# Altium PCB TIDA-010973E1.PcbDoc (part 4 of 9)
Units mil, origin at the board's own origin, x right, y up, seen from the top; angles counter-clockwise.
Board outline 5166 x 3669 mil, 8 copper layers (L01 - TOP, L02 - GND, L03 - SIG, L04 - GND, L05 - PWR, L06 - SIG, L07 - GND, L08 - BOTTOM), stack 61.7 mil thick; 677 components, 493 nets, 2522 pads, 1424 vias.
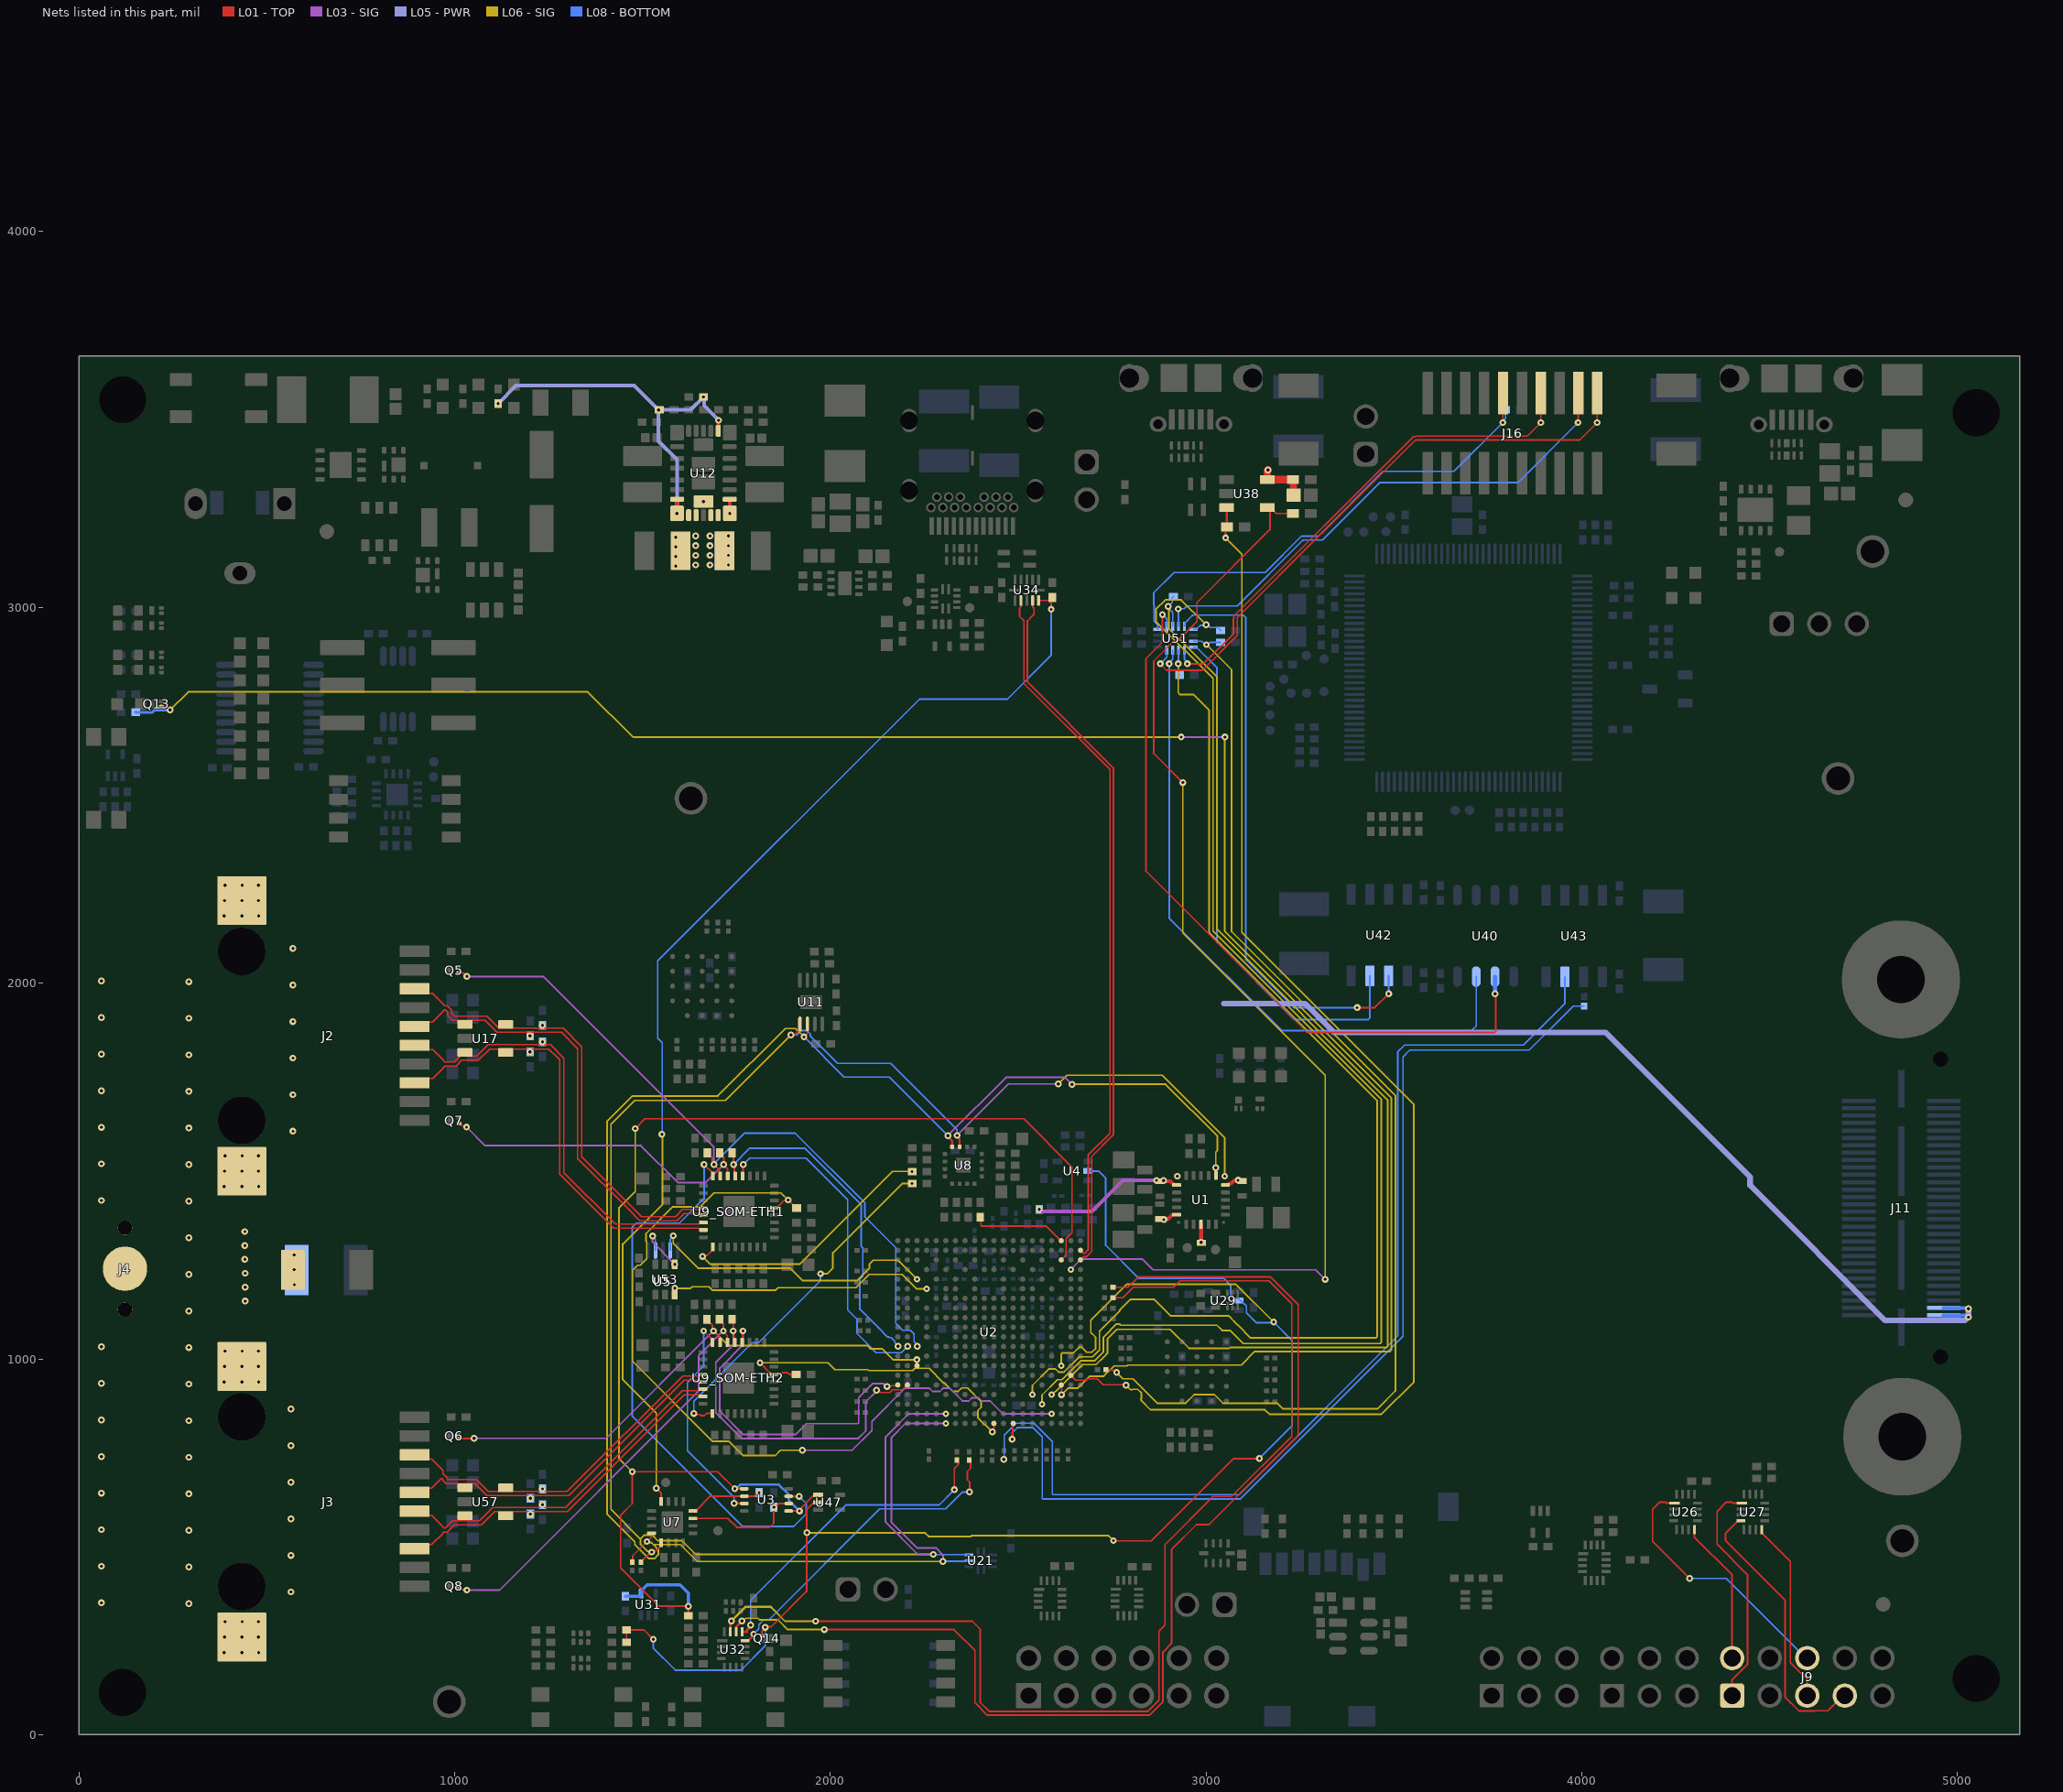
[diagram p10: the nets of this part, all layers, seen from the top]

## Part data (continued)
R167: library part CMP-0026413-2, "RES, 4.87 k, 1%, 0.063 W, AEC-Q200 Grade 0, 0402", Manufacturer=Vishay-Dale, Power_W=63mW, Supplier Part Number 1=541-4.87KLCT-ND, TempCo="100 ppm/C", Tolerance_%=1%, Value2=0.063W, Value_Code=4k87, ValueDisplayed=4.87k
R168: library part CMP-0078244-2, "RES, 30.0 k, 1%, 0.063 W, AEC-Q200 Grade 0, 0402", Manufacturer=Vishay-Dale, Power_W=63mW, Supplier Part Number 1=541-30.0KLCT-ND, TempCo="100 ppm/C", Tolerance_%=1%, Value2=0.063W, Value_Code=30k0, ValueDisplayed=30.0k
R216: library part CMP-0026022-3, "RES, 150, 1%, 0.063 W, AEC-Q200 Grade 0, 0402", Manufacturer=Vishay-Dale, Power_W=63mW, Supplier Part Number 1=541-150LCT-ND, TempCo="100 ppm/C", Tolerance_%=1%, Value2=0.063W, Value_Code=150R, ValueDisplayed=150
R218: library part CMP-0027615-1, "RES, 33.0, 1%, 0.05 W, 0201", Manufacturer="Yageo America", Power_W=50mW, Supplier Part Number 1=311-33.0MCT-ND, TempCo="200 ppm/C", Tolerance_%=1%, Value2=0.05W, Value_Code=33R0, ValueDisplayed=33.0
R222: library part CMP-0093210-1, "Jumper 0.063W, 1/16W Chip Resistor 0402 (1005 Metric) - Thick Film", Digikey Part Number=541-4062-1-ND, Manufacturer=Vishay, Mouser Part Number=71-CRCW04020000Z0EDC, Operating Temperature Range="-55°C to +155°C", Power_W=63mW
SH-J1 SH-J2: library part CMP-0003761-2, "Shunt, 2.54mm, Gold, Black", Manufacturer="Wurth Elektronik", Supplier Part Number 1=732-2678-ND
SW1 SW6: library part CMP-0093176-1, "Dip Switch SPST 4 Position Surface Mount Slide (Standard) Actuator 25mA 24VDC", Coil Resistance_ohm=100mΩ, Contact Current Rating=25mA, Digikey Part Number=732-3854-1-ND, Manufacturer=Wurth, Mouser Part Number=710-416131160804, Operating Temperature Range="-40°C to +85°C"
SW2 SW4 SW5: library part CMP-0093456-1, "Tactile Switch SPST-NO Side Actuated Surface Mount, Right Angle", Coil Resistance_ohm=100mΩ, Contact Current Rating=50mA, Digikey Part Number=732-7057-1-ND, Manufacturer="Wurth Electronics", Mouser Part Number=710-434351045816, Operating Force=160gf, Operating Temperature Range="-40°C to +85°C"
SW3: library part CMP-0124547-1, "Dip Switch Hexadecimal 16 Position Surface Mount Rotary for Tool Actuator 100mA 42VDC", Coil Resistance_ohm=80mΩ, Contact Current Rating=100mA, CurrentRating_mA=400mA, Digikey Part Number=732-6989-1-ND, Manufacturer=Wurth, Mouser Part Number=710-428542320816, Operating Force=150gf, Operating Temperature Range="-60°C to +125°C"
TP1 TP6 TP7 TP8 TP9 TP10 TP11 TP12 TP13 TP14 TP15 TP16 TP17 TP18 TP19 TP20 TP21 TP22 TP23 TP24 TP25 TP26 TP27 TP29 TP30 TP32 TP33: library part CMP-0078143-4, "TEST POINT.  No entry in BOM.", Manufacturer=N/A
TP2 TP3 TP4 TP5 TP31: library part CMP-0055148-2, "Test Point, Multipurpose, Black, TH", Color=Black, Manufacturer="Keystone Electronics", Supplier Part Number 1=36-5011-ND
U1: library part CMP-0121651-1, "Integrated Power Management IC for ARM Cortex®—Low Power Processors and FPGAs", Manufacturer="Texas Instruments", Max Supply Voltage=5.5V, Min Supply Voltage=2.5V, Operating Temperature Range="-40°C to +125°C", Output Voltage=0.6-3.4/0.6-3.4/0.6-3.3/0.6-3.3V
U2: library part CMP-0126016-1, "ARM® Cortex®-R5F Sitara™ Microcontroller IC 32-Bit Dual-Core 500MHz 512KB (512K x 8) Tightly Coupled Memory (TCM) 304-NFBGA (13.25x13.25)", Digikey Part Number=296-AM2612AOFFHIZFGRCT-ND, Frequency_Fixed=500MHz, Manufacturer="Texas Instruments", Max Supply Voltage=3.465V, Min Supply Voltage=1.14V, Mouser Part Number=595-AM2612AOFFHIZFGR, Operating Temperature Range="-40°C to +125°C"
U3: library part CMP-0051796-2, "Dual 2-Input Positive-AND Gate, DCU0008A (VSSOP-8)", F @ Nom Voltage(Max)(Mhz)=150, Generic Part Number=SN74LVC2G08, ICC @ Nom Voltage(Max)(mA)=0.01, Manufacturer="Texas Instruments", Operating Temperature Range="-40 to 125 C", Rating=Catalog, tpd @ Nom Voltage(Max)(ns)=9.8,5.8,5.3,4.8, Voltage(Nom)(V)=1.8,2.5,3.3,5
U4 U29: library part CMP-0051263-2, "Single 2-Input Positive–AND Gate with Open Drain Output, DCK0005A, LARGE T&R", F @ Nom Voltage(Max)(Mhz)=75, Generic Part Number=SN74AHC1G09, ICC @ Nom Voltage(Max)(mA)=0.01, Manufacturer="Texas Instruments", Operating Temperature Range(C)="-40 to 85", Rating=Catalog, tpd @ Nom Voltage(Max)(ns)=11,7.5, Voltage(Nom)(V)=3.3,5
U5: library part CMP-0067419-2, "2-Channel, 2:1 Analog Switch with Low On-State Resistance (1ohm) and Powered Off Protection, DGS0010A (VSSOP-10)", Alternate Manufacturer="Texas Instruments", Alternate PartNumber=TS5A23159DGST, Operating Temperature Range="-40 to 85 C", Rating=Catalog
U6: library part CMP-0051428-5, "Single Bus Buffer Gate With 3-State Outputs, DSF0006A, LARGE T&R", Alternate Manufacturer="Texas Instruments", F @ Nom Voltage(Max)(Mhz)=150, Generic Part Number=SN74LVC1G125, ICC @ Nom Voltage(Max)(mA)=0.01, Operating Temperature Range(C)="-40 to 125,-40 to 85", Rating=Catalog, tpd @ Nom Voltage(Max)(ns)=9,5.5,4.5,4, Voltage(Nom)(V)=1.8,2.5,3.3,5
U7 U23: library part CMP-0043157-2, "Low-Voltage 8-Bit I2C and SMBus I/O Expander, 1.65 to 5.5 V, -40 to 85 degC, 16-pin QFN (RGT), Green (RoHS & no Sb/Br)", 5V Tolerant I/O=Yes, Manufacturer="Texas Instruments", Max Frequency(kHz)=400
U8: library part CMP-0126121-1, "5 output reference-less clock generator with bulk acoustic wave (BAW) 16-TQFN -40 to 85", Digikey Part Number=296-LMK3C0105V33RERRTR-ND, Manufacturer="Texas Instruments", Max Frequency=200MHz, Max Supply Voltage=3.465V, Min Supply Voltage=1.71V, Mouser Part Number=595-LMK3C0105V33RERR, Operating Temperature Range="-40°C to +85°C"
U9_SOM-ETH1 U9_SOM-ETH2: library part CMP-0124715-2, "Deterministic, Low-Latency, Low-Power, 10/100 Mbps, Industrial Ethernet PHY", Manufacturer="Texas Instruments", Max Supply Voltage=3.6V, Min Supply Voltage=1.62V, Operating Temperature Range="-40°C to +85°C"
U10: library part CMP-0122153-1, "1.8V 64M-BIT [x 1/x 8] Read-While-Write octaflash Memory", Frequency_Fixed=200MHz, Manufacturer=Macronix, Max Supply Voltage=2V, Min Supply Voltage=1.7V, Nominal Supply Current=18-140mA, Operating Temperature Range="-40°C to +125°C"
U11: library part CMP-0126419-1, "EEPROM Serial-I2C 1M-bit 128K x 8 2.5V/3.3V/5V 8-Pin UDFN EP T/R", Digikey Part Number=CAT24M01HU5I-GT3OSCT-ND, Frequency_Fixed=1MHz, Manufacturer=onsemi, Max Supply Voltage=5.5V, Min Supply Voltage=1.8V, Mouser Part Number=863-CAT24M01HU5I-GT3, Nominal Supply Current=1-5mA, Operating Temperature Range="-40°C to +85°C"
U12: library part CMP-0092030-4, "3-V to 36-V Input, 1-V to 6-V Output, 3-A Power Module", Manufacturer="Texas Instruments", Max Supply Voltage=36V, Min Supply Voltage=3V, Operating Temperature Range=to, Output Voltage=1-6V, Switching Frequency=200-2200kHz
U13: library part CMP-0081714-3, "33 V Bidirectional Flat-Clamp Surge Protection Device, DRB0008A (VSON-8)", Alternate Manufacturer="Texas Instruments", Alternate PartNumber=TVS3301DRBR, Operating Temperature Range="-40 to 125 C", Rating=Catalog
U14 U15: library part CMP-0013281-4, "Low Iq Always ON Smart Diode Controller, DBV0006A (SOT-23-6)", Alternate Manufacturer="Texas Instruments", Alternate PartNumber=LM74700QDBVTQ1
U16: library part CMP-0122758-1, "DRAM IoT RAM 128Mb OPI (x8) DDR 200MHz, 1.8V, Ext. Temp., BGA24", Frequency_Fixed=200MHz, Manufacturer="AP Memory", Max Supply Voltage=1.98V, Min Supply Voltage=1.62V, Mouser Part Number=878-APS12808L-OBMXBA, Nominal Supply Current=4-22mA, Operating Temperature Range="-40°C to +105°C"
U17 U57: library part CMP-0085635-1, "Data-Line Surge and ESD Protection Diode Array, DBV0005A (SOT-23-5)", Alternate Manufacturer="Texas Instruments", Operating Temperature Range="-40 to 125 C", Rating=Catalog
U19: library part CMP-0043123-1, "Low-Capacitance + / - 15 kV ESD Protection Array for High-Speed Data Interfaces, 6 Channels, -40 to +85 degC, 10-pin UQFN (RSE), Green (RoHS & no Sb/Br)", Breakdown Voltage(Min)(V)=11, IO Capacitance(Typ)(pF)=1.5, IO Leakage Current(nA)=1, Manufacturer="Texas Instruments"
U20: library part CMP-0051412-4, "Single Buffer/Driver With Open-Drain Output, DRY0006A (USON-6)", F @ Nom Voltage(Max)(Mhz)=150, Generic Part Number=SN74LVC1G07, ICC @ Nom Voltage(Max)(mA)=0.01, Manufacturer="Texas Instruments", Operating Temperature Range="-40 to 125 C", Operating Temperature Range(C)="-40 to 125,-40 to 85", Rating=Catalog, tpd @ Nom Voltage(Max)(ns)=8.6,6,4.7,4, Voltage(Nom)(V)=1.8,2.5,3.3,5
U21: library part CMP-0122684-1, "2-pF, 3.3-V, 2:1 (SPDT), 2-channel, switch with 1.8-V compatible logic", Digikey Part Number=296-TMUX121NKGRCT-ND, Manufacturer="Texas Instruments", Max Supply Voltage=3.6V, Min Supply Voltage=3V, Mouser Part Number=595-TMUX121NKGR, Nominal Supply Current=1.3-11uA, On State Resistance=3.9Ω, Operating Temperature Range="-40°C to +125°C"
U22: library part CMP-0034642-1, "8-Bit Fast Mode Plus (FM+) I2C Bus Constant-Current LED Sink Driver, 3 to 5.5 V, -40 to 85 degC, 20-pin SOP (PW20), Green (RoHS & no Sb/Br)", Manufacturer="Texas Instruments"
U24: library part CMP-0043237-2, "Remote 4-Bit I2C and SMBus I/O Expander With Configuration Registers, DGK0008A (VSSOP-8)", 5V Tolerant I/O=Yes, Manufacturer="Texas Instruments", Max Frequency(kHz)=400
U25: library part CMP-0051707-3, "Single Schmitt-Trigger Buffer, DRL0005A, LARGE T&R", Alternate Manufacturer="Texas Instruments", F @ Nom Voltage(Max)(Mhz)=150, Generic Part Number=SN74LVC1G17, ICC @ Nom Voltage(Max)(mA)=0.01, Operating Temperature Range(C)="-40 to 125,-40 to 85", Rating=Catalog, tpd @ Nom Voltage(Max)(ns)=11,6.5,5.5,5, Voltage(Nom)(V)=1.8,2.5,3.3,5
U26 U27 U28 U49 U51 U52: library part CMP-0086167-3, "Low-capacitance, 2:1 (SPDT) 4-channel, powered-off protection switch with 1.8 V logic, RSV0016A (UQFN-16)", Alternate Manufacturer="Texas Instruments", Operating Temperature Range="-40 to 125 C", Rating=Catalog
U30: library part CMP-0051441-4, "Single Schmitt-Trigger Buffer, DRY0006A (USON-6)", F @ Nom Voltage(Max)(Mhz)=150, Generic Part Number=SN74LVC1G17, ICC @ Nom Voltage(Max)(mA)=0.01, Manufacturer="Texas Instruments", Operating Temperature Range="-40 to 125 C", Operating Temperature Range(C)="-40 to 125,-40 to 85", Rating=Catalog, tpd @ Nom Voltage(Max)(ns)=11,6.5,5.5,5, Voltage(Nom)(V)=1.8,2.5,3.3,5
U31: library part CMP-0051585-3, "Single 2-Input Positive-AND Gate, DRL0005A, LARGE T&R", Alternate Manufacturer="Texas Instruments", F @ Nom Voltage(Max)(Mhz)=150, Generic Part Number=SN74LVC1G08, ICC @ Nom Voltage(Max)(mA)=0.01, Operating Temperature Range(C)="-40 to 125,-40 to 85", Rating=Catalog, tpd @ Nom Voltage(Max)(ns)=4.5,6,4,5, Voltage(Nom)(V)=1.8,2.5,3.3,5
U32: library part CMP-0066450-2, "4-Bit Dual-Supply Bus Transceiver with Configurable Voltage-Level Shifting and 3-State Outputs, RSV0016A (UQFN-16)", Alternate Manufacturer="Texas Instruments"
U33: library part CMP-0073635-2, "USB Type-C Configuration Channel Logic and Port Control, RWB0012A (X2QFN-12)", Alternate Manufacturer="Texas Instruments", Operating Temperature Range="-40 to 85 C", Rating=Catalog
U34: library part CMP-0033722-2, "USB 2.0 High-Speed (480 Mbps) and Audio Switch, DP3T, 6.5 ohm RON, -40 to 85 degC, 12-Pin UQFN (RUT), Green (RoHS & no Sb/Br)", Manufacturer="Texas Instruments"
U35 U36 U44: library part CMP-0073612-3, "4-Channel ESD Protection Diode for USB Type-C and HDMI 2.0, DQA0010A (USON-10)", Alternate Manufacturer="Texas Instruments"
U37: library part CMP-0073678-3, "5.5V, 4A, 16mΩ Automotive Load Switch With Adjustable Rise Time and Optional Quick Output Discharge, DSG0008B (WSON-8)", Alternate Manufacturer="Texas Instruments", Alternate PartNumber=TPS22965TDSGTQ1
U38: library part CMP-0074276-1, "Single, Current-Limited, Power-Distribution Switch, DBV0005A (SOT-23-5)", Alternate Manufacturer="Texas Instruments", Alternate PartNumber=TPS2051BDBVT
U39: library part CMP-0051530-2, "Single 2-Input Positive-NOR Gate, DRL0005A, LARGE T&R", Alternate Manufacturer="Texas Instruments", F @ Nom Voltage(Max)(Mhz)=75, Generic Part Number=SN74AHC1G02, ICC @ Nom Voltage(Max)(mA)=0.01, Operating Temperature Range(C)="-40 to 125,-40 to 85", Rating=Catalog, tpd @ Nom Voltage(Max)(ns)=11.4,7.5, Voltage(Nom)(V)=3.3,5
U40: library part CMP-0029369-1, "25 Mbps Dual Channels, 2 / 0, Digital Isolator, 3.3 V / 5 V, -40 to +125 degC, 8-pin SOIC (D), Green (RoHS & no Sb/Br)", Insulation Rating(VRMS)=2500, Manufacturer="Texas Instruments", Rating=Catalog, Supply Voltage(s)(V)="3.3, 5"
U41: library part CMP-0029856-2, "Tiva C Series Microcontroller, 1024 KB Flash, 256 KB SRAM, 12 Bit, 20 Channels, -40 to 105 degC, 128-Pin TQFP (PDT), Green (RoHS & no Sb/Br), Tray", Manufacturer="Texas Instruments", Temperature Range="-40 to 105 degC"
U42 U43: library part CMP-0076059-2, "High Speed, Robust EMC Dual-Channel Digital Isolator, D0008B (SOIC-8)", Alternate Manufacturer="Texas Instruments", Alternate PartNumber=ISO7721D, Operating Temperature Range="-55 to 125 C", Rating=Catalog
U45: library part CMP-0036402-3, "Single Output High PSRR LDO, 1 A, Adjustable 1.2 to 5.5 V Output, 2.7 to 5.5 V Input, 8-pin SON (DRB), -40 to 125 degC, Green (RoHS & no Sb/Br)", Manufacturer="Texas Instruments"
U46: library part CMP-0033001-1, "Precision Micropower Shunt Voltage Reference, 0.5% accuracy, 2.5 V, 15 ppm / degC, 15 mA, -40 to 125 degC, 3-pin SOT-23 (DBZ), Green (RoHS & no Sb/Br)", Manufacturer="Texas Instruments", Rating=Catalog, Temp Coeff(Max)(ppm/ degree C)=100, Temp Coeff(Typ)(ppm/ degree C)=15
U47: library part CMP-0051558-2, "Single 2-Input Positive-AND Gate, DRL0005A, LARGE T&R", Alternate Manufacturer="Texas Instruments", F @ Nom Voltage(Max)(Mhz)=75, Generic Part Number=SN74AHC1G08, ICC @ Nom Voltage(Max)(mA)=0.01, Operating Temperature Range(C)="-55 to 125", Rating=Catalog, tpd @ Nom Voltage(Max)(ns)=12.3,7.9, Voltage(Nom)(V)=3.3,5
U48: library part CMP-0051903-4, "Dual Schmitt-Trigger Buffer, DRY0006A (USON-6)", F @ Nom Voltage(Max)(Mhz)=150, Generic Part Number=SN74LVC2G17, ICC @ Nom Voltage(Max)(mA)=0.01, Manufacturer="Texas Instruments", Operating Temperature Range="-40 to 125 C", Operating Temperature Range(C)="-40 to 125,-40 to 85", Rating=Catalog, tpd @ Nom Voltage(Max)(ns)=9.3,5.7,5.4,4.3, Voltage(Nom)(V)=1.8,2.5,3.3,5
U50: library part CMP-0122847-1, "5.5-V, 2-A, 52-mΩ load switch with adj. rise time and adj. output discharge", Digikey Part Number=296-46278-1-ND, Manufacturer="Texas Instruments", Max Supply Voltage=5.5V, Mouser Part Number=595-TPS22918DBVR, Nominal Supply Current=8.3-10.2uA, Operating Temperature Range="-40°C to +105°C"
U53: library part CMP-0074352-3, "1-Bit Bidirectional Voltage-Level Shifter for Open-Drain and Push-Pull Application, DCK0006A (SOT-SC70-6)", Alternate Manufacturer="Texas Instruments", Alternate PartNumber=TXS0101DCKT, Operating Temperature Range="-40 to 85,-55 to 125 C", Rating=Catalog
U54: library part CMP-0051682-2, "Single Inverter Gate, DRL0005A, LARGE T&R", Alternate Manufacturer="Texas Instruments", F @ Nom Voltage(Max)(Mhz)=75, Generic Part Number=SN74AHC1G04, ICC @ Nom Voltage(Max)(mA)=0.01, Operating Temperature Range(C)="-40 to 125", Rating=Catalog, tpd @ Nom Voltage(Max)(ns)=10.6,7.5, Voltage(Nom)(V)=3.3,5
U55: library part CMP-0081179-1, "Single-Bit Dual-Supply Bus Transceiver, DRL0006A (SOT-OTHER-6)", Alternate Manufacturer="Texas Instruments"
Y1: library part CMP-0004635-3, "Crystal, 16 MHz, 8pF, SMD", Frequency Stability=+/-30ppm, Frequency_Fixed=16MHz, Manufacturer=NDK, Supplier Part Number 1=644-1157-1-ND
ZZ1: library part CMP-0003616-3
ZZ2: library part CMP-0077236-1
ZZ3: library part CMP-0077237-1
ZZ4: library part CMP-0077238-1

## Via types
v1: diameter 18, hole 8, L01 - TOP to L08 - BOTTOM, tented both sides, 1389 vias
v2: diameter 19.68, hole 7.87, L01 - TOP to L08 - BOTTOM, 24 vias
v3: diameter 19.68, hole 7.87, L01 - TOP to L08 - BOTTOM, tented both sides, 11 vias

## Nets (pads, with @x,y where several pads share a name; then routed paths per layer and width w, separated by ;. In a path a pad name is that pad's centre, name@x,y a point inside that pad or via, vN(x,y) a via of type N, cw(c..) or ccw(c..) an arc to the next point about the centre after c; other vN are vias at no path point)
5V: C22.1 C23.1 C24.1 C25.1 C88.2 C89.2 C90.2 C99.1 C135.2 C136.1 J11.2 J11.4 R1.2 R60.2 R65.2 U1.4 U1.12 U1.19 U1.20 U1.24 U12.7 U12.8 U12.9 U12.10 U12.12 U12.13 U12.14 U12.15 U12.22 U12.30 U38.5 | length 4265
  L01 - TOP w10: v1(1592.09,3250.37) 1592.31,3250.59 1592.31,3287.56 U12.7@1592.53,3287.77 ; U12.22@1701.78,3469.86 1702.39,3470.47 1702.39,3497.39 v1(1703,3498) ; U12.15@1732.29,3287.77 1732.51,3287.56 1732.51,3250.59 v1(1732.72,3250.37) ; C24.1@2877.13,1472.95 2878.97,1474.78 v1(2886.93,1474.78) ; C24.1@2886.93,1473.33 2904.53,1473.33 U1.20@2914.99,1462.87 ; v1(2887.76,1370.82) 2889.29,1372.35 2898.65,1372.35 2910.35,1384.05 U1.24@2921.8,1384.05 ; U1.4@2986.76,1358.46 2986.84,1358.38 2986.84,1310.9 v1(2987.13,1310.61) ; U1.12@3051.72,1462.79 3058.46,1462.79 3062.22,1466.55 3066.94,1466.55 3074.47,1474.08 3083.61,1474.08 v1(3085.14,1475.61)
  L01 - TOP w20: v1(3165,3366) 3163.13,3364.13 U38.5@3163.13,3340.4 3163.33,3340.2 3225.63,3340.2 3225.83,3340 C136.1@3231.38,3340 3232.35,3339.02 3232.35,3299.98 C135.2@3233.33,3299 C135.2@3232.33,3298
  L03 - SIG w10: v1(2556.15,1398.17) 2558.31,1398.17 2563.48,1393 2696.72,1393 2779,1475.28 v1(2868.11,1475.28) 2868.36,1475.03 2886.68,1475.03 v1(2886.93,1474.78)
  L05 - PWR w10: v1(1116,3542.31) 1164.02,3590.33 1478.08,3590.33 v1(1542.76,3525.65) ; v1(1592.09,3250.37) 1592.09,3393.19 1542.76,3442.53 v1(1542.76,3525.65) ; v1(1703,3498) 1664.22,3536.78 1664.22,3558.47 v1(1662.68,3560) 1628.34,3525.65 v1(1542.76,3525.65)
  L05 - PWR w15: 3048,1946 3263,1946 3340,1869 4062.82,1869 4447.75,1484.07 4447.75,1462.43 4807.68,1102.5 4847.5,1102.5 5019.69,1102.5 5028.19,1111 v1(5029,1111) v1(5029,1134)
  L08 - BOTTOM w10: J11.2@4962.8,1116.05 5021.79,1116.05 5026.84,1111 v1(5029,1111) ; J11.4@4962.8,1135.73 4963.29,1135.24 5027.76,1135.24 v1(5029,1134)
  other v1: 2923.77,1486.41 1589,3110 1642,3113 1680,3113 1729,3113 1589,3135.67 1642,3138.67 1680,3138.67 1729,3138.67 1589,3161.33 1642,3164.33 1680,3164.33 1729,3164.33 1589,3187 1642,3190 1680,3190 1729,3190
  other v2: 1662.41,3281.87
\ETH0_PHY_INT: R27_SOM-ETH1.2 U2.B4 U9_SOM-ETH1.21 | length 2221.1
  L01 - TOP w4.3: U9_SOM-ETH1.21@1851.13,1402.32 1858.02,1402.32 1860.79,1405.09 1860.79,1406.42 1863.31,1408.94 1865.17,1408.94 1871.09,1414.86 1871.09,1416.29 1876.28,1421.47 1886.47,1421.47 v1(1888,1423) ; v1@1888.22,1422.78 1900.79,1410.21 1900.79,1409.33 1908.48,1401.64 R27_SOM-ETH1.2@1910.45,1401.64
  L03 - SIG w4.5: v1(1926,757) 2057.85,757 2110.85,810 2110.85,834.1 2199.2,922.45 2263.54,922.45 2272.27,913.72 2291.78,913.72 2300.49,922.43 2317.37,922.43 2351.67,888.13 2368.55,888.13 2377.26,896.84 2394.14,896.84 2402.85,888.13 2425.77,888.13 2459.8,854.09 v1(2589.09,854.09)
  L06 - SIG w4.5: v1(1888,1423) 1868.93,1442.07 1690.91,1442.07 1653.23,1404.39 1579.99,1404.39 1509.75,1334.15 1509.75,1313.65 1511.25,1312.15 1511.25,1266.22 1494.45,1249.42 1487,1249.42 1473.47,1235.89 1473.47,994.13 1686.91,780.7 1730.7,780.7 1768.65,742.75 1853.15,742.75 1867.4,757 v1(1926,757)
\ETH1_PHY_INT: R27_SOM-ETH2.2 U2.A10 U9_SOM-ETH2.21 | length 882.4
  L01 - TOP w4.3: v1(1813,990) 1826.79,976.21 1826.79,975.25 1836.1,965.94 1836.63,965.94 1843.24,959.32 1867.57,959.32 1872.03,963.79 1886.24,963.79 1891.39,958.64 R27_SOM-ETH2.2@1909.45,958.64 ; v1(2431,806) 2431,809.71 2435.54,814.25 U2.A10@2435.54,828.5
  L06 - SIG w4.5: v1(1813,990) 1994,990 2012.25,971.75 2100.54,971.75 2103.26,969.03 2218.78,969.03 2224.9,975.15 2263.1,975.15 2301.48,936.77 2303.02,936.77 2326.08,913.72 2340.28,913.72 2349.63,923.06 2365.24,923.06 2401.51,886.79 2401.51,871.24 2392.8,862.54 2392.8,844.2 v1(2431,806)
\PHY_RESET_SOM-ETH1: U3.7 U9_SOM-ETH1.32 | length 1537.9
  L01 - TOP w4.3: v1(1664.13,1517.64) 1664.13,1517.47 1687.75,1493.86 U9_SOM-ETH1.32@1687.75,1486.97
  L01 - TOP w6: U3.7@1889.18,634.84 1889.34,634.68 1916.81,634.68 v1(1916.98,634.52)
  L08 - BOTTOM w4.3: v1(1664.13,1517.64) 1664.13,1427.18 1598.63,1361.68 1483.68,1361.68 1472.72,1350.72 1472.72,848.32 1767.04,554 1901.91,554 1935.98,588.06 1935.98,615.52 v1(1916.98,634.52)
\PHY_RESET_SOM-ETH2: U3.3 U9_SOM-ETH2.32 | length 595.9
  L01 - TOP w4.3: v1(1663.13,1074.64) 1663.13,1074.47 1686.75,1050.86 U9_SOM-ETH2.32@1686.75,1043.97
  L01 - TOP w6: v1@1744.16,615.34 1770.89,615.34 U3.3@1771.07,615.16
  L08 - BOTTOM w4.3: v1(1663.13,1074.64) 1663.13,981.06 1619.85,937.77 1619.85,756.15 1743.98,632.02 v1(1743.98,615.52)
AM261_ETH0_RST: R6.1 U3.2 U7.4 | length 196.3
  L01 - TOP w4.5: U7.4@1634.59,595.41 1641.68,595.41 1681.11,634.84 U3.2@1771.07,634.84 1798.01,634.84 1807.85,644.68 v1(1810.44,644.68)
AM261_ETH1_RST: R14.1 U3.6 U7.3 | length 315.5
  L01 - TOP w4.5: U7.3@1634.59,575.72 1727.28,575.72 1751,552 1838.96,552 1849.81,562.85 v1(1849.81,605.32) 1853.06,605.32 1862.9,615.16 U3.6@1889.18,615.16
AM261_I2C0.SCL: R219.1 U1.14 U2.A15 U7.12 U8.4 U11.6 U21.4 | length 4979.4
  L01 - TOP w4.3: R219.1@1473,459.02 1474.27,460.29 1474.27,476.27 v1(1512,514) 1524.35,526.35 U7.12@1524.35,536.35 ; v1(1930,1857) 1939.13,1866.13 U11.6@1939.13,1891.42
  L01 - TOP w6: v1(2313.37,1593.91) 2313.37,1590.81 2324.49,1579.69 U8.4@2324.49,1564.79
  L01 - TOP w8: v1(3026,1509) 3026.07,1508.93 U1.14@3026.13,1488.38 U1.14@3026.13,1488.38
  L03 - SIG w4.5: v1(2300,461) 2300,478.4 2281.15,497.25 2230.75,497.25 2163,565 2163,776.34 2163,791.25 2200.25,828.5 v1(2307.59,828.5) ; v1(2313.37,1593.91) 2313.37,1595.31 2467.31,1749.25 2624.75,1749.25 v1(2643,1731)
  L06 - SIG w4.5: v1(1512,514) 1514.58,511.42 1523.98,511.42 1529.39,506 ; v1(1930,1857) 1907.75,1879.25 1880.31,1879.25 1700.81,1699.75 1473.75,1699.75 1405.81,1631.81 1405.81,587.58 1479.91,513.48 1479.91,506.69 1517.86,468.75 1532.14,468.75 1542.25,478.86 1542.25,493.14 1529.39,506 ; v1(2300,461) 1646,461 1601,506 1529.39,506 ; v1(2643,1731) 2892.4,1731 3030.25,1593.15 3030.25,1555.02 3026,1550.77 v1(3026,1509)
  L08 - BOTTOM w4.3: v1(2300,461) 2301,462 2368.5,462 U21.4@2369.5,463
  L08 - BOTTOM w4.5: v1(1930,1857) 2037,1750 2157.28,1750 v1(2313.37,1593.91)
AM261_I2C0.SDA: R17.1 U1.13 U2.B15 U7.13 U8.3 U11.5 U21.5 | length 4925.4
  L01 - TOP w3.5: v1(1525,486) 1527.77,488.77 1535.04,488.77 1549.94,503.68 U7.13@1549.94,510.76 ; v1(1895,1862) 1897.77,1864.77 1907.86,1864.77 1919.45,1876.36 U11.5@1919.45,1891.42
  L01 - TOP w4.5: R17.1@1496,459.02 1496,459.81 1522.19,486 v1(1525,486)
  L01 - TOP w6: v1(2337.37,1594.91) 2337.37,1591.67 2344.17,1584.86 U8.3@2344.17,1564.79
  L03 - SIG w4.5: v1(2274,480) 2233,480 2147,566 2147,776.34 2147,792.33 2208.76,854.09 v1(2307.59,854.09) ; v1(2337.37,1594.91) 2474.46,1732 v1(2607,1732)
  L06 - SIG w4.5: v1(1525,486) 1522.42,488.58 1513.02,488.58 1494.75,506.86 1494.75,521.14 ; v1(1895,1862) 1721,1688 1480,1688 1416.31,1624.31 1416.31,599.58 1494.75,521.14 ; v1(2274,480) 1641.85,480 1605.35,516.5 1540.5,516.5 1525.75,531.25 1504.86,531.25 1494.75,521.14 ; v1(2607,1732) 2630,1755 2883.24,1755 3049.76,1588.49 v1(3049.76,1486.41)
  L08 - BOTTOM w4.3: v1(2274,480) 2274.63,479.37 2368.88,479.37 U21.5@2369.5,478.75
  L08 - BOTTOM w4.5: v1(1895,1862) 1895.15,1862.15 1910.75,1862.15 1922.85,1874.25 1937.15,1874.25 1947.25,1864.15 1947.25,1858.75 2019.33,1786.67 2161.18,1786.67 2337.37,1610.48 v1(2337.37,1594.91)
AM261_PORZN: R122.1 R181.1 U2.V3 U3.1 U3.5 U31.4 U47.1 | length 3801.5
  L01 - TOP w3.5: v1(1481,1613) 1507,1639 2514.92,1639 2642.09,1511.83 2643.12,1510.8 2643.12,1335.36 2627.69,1319.93 2627.69,1283.92 2627.9,1279.67 2627.9,1276.77 2626.87,1275.74 U2.V3@2614.68,1263.54
  L01 - TOP w4.5: v1(1622,342) 1544.34,342 1441.85,444.49 1441.85,584.05 1473,615.2 v1(1473,700) 1700.5,700 v1(1745.98,654.52) ; U3.5@1889.18,595.47 v1(1917.98,595.52) ; v1@1920.27,601.62 1953.87,635.22 1964.87,635.22 U47.1@1967.77,638.13
  L01 - TOP w6: v1(1622,342) 1622,317.02 R122.1@1622.55,316.46 ; v1(1745.98,654.52) U3.1@1771.07,654.53
  L06 - SIG w4.5: v1(1473,700) 1437.31,735.69 1437.31,1401.97 1481,1445.66 v1(1481,1613)
  L08 - BOTTOM w6: v1(1745.98,654.52) 1749.22,654.52 1760.2,665.5 1863.38,665.5 1889.53,639.35 1889.53,623.97 v1(1917.98,595.52)
  L08 - BOTTOM w8: R181.1@1455,368.68 1494.57,368.68 1496.47,370.59 U31.4@1496.47,375.75 1496.47,383.03 1512.38,398.94 1599.93,398.94 1622,376.87 v1(1622,342)
AM261_SAFETY_ERR: Q13.1 R213.1 U2.E3 | length 5766.8
  L01 - TOP w3.5: v1@2614.84,905.16 U2.E3@2614.84,930.7
  L01 - TOP w4.5: U2.E3@2614.68,930.87 U2.E3@2614.84,930.7 ; v1@2614.84,905.16 v1(2615,905)
  L01 - TOP w6: Q13.1@219.8,2736.11 233.89,2736.11 v1(243,2727)
  L03 - SIG w4.5: v1(2934,2655) v1(3050,2655)
  L06 - SIG w4.5: v1(243,2727) 291.24,2775.24 1025.36,2775.24 1025.85,2774.75 1040.15,2774.75 1040.64,2775.24 1354.73,2775.24 1474.98,2655 v1(2934,2655) ; v1(2615,905) 2615.74,905 2633.16,922.43 2658.95,922.43 2690.76,954.23 2727.84,954.23 2754.85,981.25 2789,981.25 2791.59,983.84 3093.84,983.84 3130,1020 3489.36,1020 3493.5,1024.14 3493.5,1694 3050,2137.5 v1(3050,2655)
  L08 - BOTTOM w8: R213.1@151.68,2721.22 152.3,2720.61 195,2720.61 201.39,2727 v1(243,2727)
AM261_SOP0: R16.1 U32.15 | length 3175.8
  L01 - TOP w4.3: v1(1961,302) 2378,302 2399,281 2399,86 2422.61,62.39 2845.24,62.39 2875,92.15 2875,276 2890.65,291.65 2890.65,505.65 3019,634 3068,634 3228.15,794.15 3228.15,1147.1 3167.45,1207.8 2930.55,1207.8 2913.75,1191 2807,1191 2779,1163 R16.1@2752.02,1163
  L01 - TOP w6: U32.15@1733.99,273.9 1734.93,274.83 1734.93,300.93 v1(1737,303)
  L06 - SIG w4.5: 1850,332 1880,302 v1(1961,302)
  L06 - SIG w6: v1(1737,303) 1775,341 1841,341 1850,332
AM261_SOP1: R120.1 U32.14 | length 3121.9
  L01 - TOP w4.3: v1(1984,280) 2329.29,280 2384.86,224.43 2384.86,85.57 2418.35,52.09 2849.5,52.09 2885.3,87.88 2885.3,220.15 2908,242.85 2908,493.25 2974,559.25 3007.82,559.25 3245,796.43 3245,1144.82 3171.72,1218.1 2819.54,1218.1 2792.43,1191 R120.1@2752.02,1191
  L01 - TOP w6: U32.14@1749.74,273.9 1750.68,274.83 1750.68,288.68 v1(1765,303)
  L06 - SIG w4.5: v1(1765,303) 1768.25,303 1775.25,310 1807.6,310 1811.85,305.75 1861.4,305.75 1887.15,280 v1(1984,280)
AM261_SOP2: R121.1 U32.13 | length 851
  L01 - TOP w4.3: v1(2330,652) 2330,708.53 2340.42,718.95 2340.42,733.56 R121.1@2340,733.98
  L01 - TOP w6: U32.13@1765.49,273.9 1777.9,273.9 1778.43,274.43 1778.43,279.18 1788,288.75 v1(1788,292)
  L08 - BOTTOM w4.3: v1(1788,292) 1788,358.11 2041.19,611.3 2289.3,611.3 v1(2330,652)
AM261_SOP3: R123.1 U32.12 | length 863.6
  L01 - TOP w4.3: v1(2370.48,646) 2371,646.52 2371,672.21 2365,678.21 2365,700.71 2373.42,709.12 2373.42,733.56 R123.1@2373,733.98
  L01 - TOP w6: U32.12@1773.36,250.28 1781.24,250.28 1796,265.04 v1(1796,268)
  L08 - BOTTOM w4.3: v1(1796,268) 1809.95,281.95 1809.95,293.06 1822.66,305.78 1836.78,305.78 2132,601 2307,601 2352,646 v1(2370.48,646)
AM261_TCK: R239.1 U2.D4 U51.2 | length 3313.7
  L06 - SIG w4.5: v1(2589.09,905.28) 2591.02,905.28 2607.9,922.15 2608.45,922.15 2671.18,984.88 2707.26,984.88 2729.83,1007.46 2737.35,1014.97 2737.35,1053.54 2762.81,1079 2904.31,1079 2955.03,1028.28 3061.4,1028.28 3063.62,1030.5 3480.36,1030.5 3483,1033.14 3483,1689.65 3029.25,2143.4 3029.25,2815.35 2901.25,2943.35 2901.25,3000.75 v1(2899,3003)
  L08 - BOTTOM w4.3: U51.2@2911.13,2949.5 2911.13,2987.17 2899,2999.29 v1(2899,3003) 2909.92,3013.92 2909.92,3025.61 R239.1@2913.32,3029
AM261_TCK_JTAG: J16.11 R186.1 U51.16 | length 1334.1
  L01 - TOP w4.3: v1(3789.93,3492) 3789.93,3569.77 J16.11@3790.43,3570.28
  L08 - BOTTOM w4.3: U51.16@2871.76,2941.62 2871.76,2952.91 2862,2962.66 2862,2965 2862,3004.45 2860.78,3005.66 2860.78,3038.78 2915,3093 3157,3093 3253,3189 3253.43,3189 3254.03,3189.6 3298.6,3189.6 3471,3362 3659.93,3362 v1(3789.93,3492) 3789.93,3495.71 3797.31,3503.1 R186.1@3797.31,3526
AM261_TCK_XDS: U40.6 U51.1 | length 1996
  L01 - TOP w4.3: v1(2884,2981) 2884,2908 2840,2864 2840,2298 3269,1869 3768.48,1869 3771,1871.52 3771,1970 v1(3769,1972)
  L08 - BOTTOM w4.3: v1(2884,2981) 2895.38,2969.62 U51.1@2895.38,2947.53
  L08 - BOTTOM w10: v1(3769,1972) U40.6@3769,2017.5
AM261_TDI: R240.1 U2.C5 U51.5 | length 3504.9
  L06 - SIG w4.5: v1(2563.5,879.69) 2563.5,903.94 2604.37,944.82 2616.41,944.82 2666.87,995.28 2702.95,995.28 2726.95,1019.28 2726.95,1057.91 2729.83,1060.8 2762.03,1092.99 2769.76,1092.99 2772.9,1089.85 3028.9,1089.85 3042.74,1076 3064.18,1076 3099.18,1041 3463.36,1041 3466,1043.64 3466,1691.8 3018.75,2139.05 3018.75,2811 2866.75,2963 2866.75,2995.15 2891.85,3020.25 2933.75,3020.25 v1(3000,2954)
  L08 - BOTTOM w4.3: U51.5@2966.24,2941.62 2974.12,2941.62 2984.55,2952.05 2998.05,2952.05 v1(3000,2954) 3003.71,2954 3011.01,2946.69 3030.94,2946.69 R240.1@3038.63,2939
AM261_TDI_JTAG: J16.3 U51.3 | length 1394.8
  L01 - TOP w4.3: v1(3990,3492) 3990,3569.84 J16.3@3990.43,3570.28
  L08 - BOTTOM w4.3: U51.3@2926.87,2949.5 2926.44,2949.93 2926.44,2995.56 v1(2926,2996) 2926.7,2996.7 2941.45,2996.7 2948.75,3004 3083,3004 3258,3179 3259.43,3179 3259.73,3179.3 3309.3,3179.3 3462,3332 3830,3332 v1(3990,3492)
AM261_TDI_XDS: U42.2 U51.4 | length 1589.6
  L01 - TOP w4.5: v1(3402,1935) 3449,1935 v1(3486,1972)
  L08 - BOTTOM w4.5: U51.4@2942.62,2949.5 2942.62,2957.37 2963,2977.75 2963,2979.36 3098.64,2979.36 3106,2972 3106,2063 3234,1935 v1(3402,1935) ; v1(3486,1972) U42.2@3486,2019.91
AM261_TDO: R212.1 R241.1 U51.7 | length 3125.1
  L01 - TOP w4.3: R212.1@2733.36,971.66 2750.63,971.66 2758.29,964 v1(2762,964)
  L06 - SIG w4.5: v1(2762,964) 2778.75,947.25 2804.99,947.25 2869.77,882.47 2945.68,882.47 2968.41,905.2 3022.07,905.2 3044.81,882.47 3189.13,882.47 3203.85,867.75 3456.75,867.75 3504,915 3504,1701 3068,2137 3068,2834 v1(3001,2901)
  L08 - BOTTOM w4.3: U51.7@2966.24,2910.13 2988.28,2910.13 2997.4,2901 v1(3001,2901) 3004.71,2901 3010.71,2907 R241.1@3038.63,2907
AM261_TDO_JTAG: J16.7 U51.9 | length 1352
  L01 - TOP w4.3: v1(2950,2850) 2993.25,2850 3073,2929.75 3073,2970 3074,2971 3074,2976.78 3552.22,3455 3558,3455 3559,3456 3855,3456 v1(3891,3492) 3891,3569.71 J16.7@3890.43,3570.28
  L08 - BOTTOM w4.3: U51.9@2942.62,2886.5 2942.62,2861.09 2950,2853.71 v1(2950,2850)
AM261_TDO_XDS: U42.3 U51.8 | length 1421.7
  L08 - BOTTOM w4.5: U51.8@2966.24,2894.38 2974.12,2894.38 3029,2839.5 3029,2109 3235,1903 3430,1903 3436,1909 U42.3@3436,2019.91
AM261_TMS: R242.1 U2.D6 U51.10 | length 3218.3
  L06 - SIG w4.5: v1(2537.91,905.28) 2537.91,929.53 2581.98,973.61 2598.86,973.61 2607.57,964.9 2621.78,964.9 2662.56,1005.68 2698.64,1005.68 2716.55,1023.59 2716.55,1073.89 2729.83,1087.18 2770.55,1127.9 2770.55,1130.08 2799.51,1159.03 2861.21,1159.03 2905.25,1115 3060,1115 3074.85,1100.15 3074.85,1099.9 3084.9,1089.85 3085.15,1089.85 3119,1056 3452.36,1056 3455,1058.64 3455,1687.95 3008,2134.95 3008,2727.4 2967.4,2768 2931,2768 2926,2773 v1(2926,2850)
  L08 - BOTTOM w4.3: U51.10@2926.87,2886.5 2926.44,2886.07 2926.44,2850.44 v1(2926,2850) 2926,2823.31 R242.1@2929.32,2820
AM261_TMS_JTAG: J16.1 U51.12 | length 1593.3
  L01 - TOP w4.3: v1(2878,2850) 2878,2849.75 2894.9,2832.85 2990.67,2832.85 3083.3,2925.48 3083.3,2972.92 3307.59,3197.22 3308.78,3197.22 3557.27,3445.7 3994.7,3445.7 v1(4041,3492) 4041,3569.71 J16.1@4040.43,3570.28
  L08 - BOTTOM w4.3: v1(2878,2850) 2878,2850.25 2895.38,2867.63 U51.12@2895.38,2886.5
AM261_TMS_XDS: U40.7 U51.11 | length 1794.6
  L08 - BOTTOM w4.3: v1(2902,2850) 2902,2853.6 2911.13,2862.72 U51.11@2911.13,2886.5
  L08 - BOTTOM w4.5: v1(2902,2850) 2902,2173 3201,1874 3707,1874 3719,1886 U40.7@3719,2017.5
AM261_UART0_RXD: R226.1 U2.A8 | length 2775.8
  L01 - TOP w3.5: v1(2484.05,786.66) 2485.39,788 v1@2485.39,793.39 ; v1@2485,793 v1@2485.39,793.39 ; U2.A8@2486.72,828.5 U2.A8@2485.86,827.64 ; v1@2485.39,793.39 2485.86,793.86 U2.A8@2485.86,827.64 ; v1@2485.39,793.39 2485.39,827.17 U2.A8@2485.86,827.64
  L08 - BOTTOM w4.3: v1(2484.05,786.66) 2484.05,803.65 2487.62,807.22 2497.75,817.35 2539.65,817.35 2564.22,792.78 2564.22,629.7 2566.74,627.18 3090.76,627.18 3524,1060.42 3524,1804 3542,1822 3860,1822 3977.01,1939.01 R226.1@4006,1939.01
AM261_UART0_TXD: R218.1 U43.3 | length 2785.3
  L08 - BOTTOM w4.5: v1(2462.1,732.6) 2462.99,733.49 2462.99,797.16 2494.83,829 2542.57,829 2591,780.57 2591,776.34 2591,641.64 2593.64,639 3087.87,639 3510,1061.13 3510,1817 3528.5,1835.5 3844.5,1835.5 3955,1946 U43.3@3955,2016.91
AM261_USB0_D_N: U2.W1 U34.8 | length 1881.5
  L01 - TOP w4.5: U34.8@2507.25,3018.44 2507.25,3001.48 2503.75,2997.97 2503.75,2976.39 2515.28,2964.86 2515.28,2797.72 2518,2795 2744.42,2568.58 2744.42,1600.58 2686.45,1542.6 2686.45,1290.44 2677,1280.99 2673.27,1280.99 2665.86,1288.41 U2.W1@2665.86,1289.13
AM261_USB0_D_P: U2.V1 U34.10 | length 1899.4
  L01 - TOP w4.5: U34.10@2538.75,3018.44 2538.75,3001.48 2542.25,2997.97 2542.25,2982.03 2524.58,2964.35 2524.58,2801.58 2751,2575.15 2753.72,2572.43 2753.72,1596.72 2751,1594 2695.75,1538.75 2695.75,1286.58 2680.85,1271.69 2673.27,1271.69 2665.86,1264.27 U2.V1@2665.86,1263.54
AM261_USB0_DRVVBUS: R142.1 U2.U2 U38.4 | length 3165
  L01 - TOP w4.5: v1(2938,2534) 2860.75,2611.25 2860.75,2857.15 2913.18,2909.57 2923.57,2909.57 2976,2962 2976,3013 3170,3207 3170,3258.73 U38.4@3163.13,3265.6 3171.01,3265.6 3186.61,3250 R142.1@3231.38,3250
  L03 - SIG w4.5: v1(2640.27,1237.95) 2668.32,1266 2729.83,1266 2830,1266 2858.85,1237.15 3291.89,1237.15 v1(3317,1212.04)
  L06 - SIG w4.5: v1(2938,2534) 2938,2134 3317,1755 v1(3317,1212.04)
AM261_USB0_MUX_SEL: R134.1 U7.8 U34.11 | length 3104.5
  L01 - TOP w4.3: U34.11@2554.5,3018.44 2583.31,3018.44 R134.1@2588,3023.13
  L01 - TOP w4.5: v1(1537,656) 1549.94,643.06 U7.8@1549.94,621 ; v1(2588,2995) 2588,3023.13 R134.1@2591,3026.13
  L06 - SIG w4.5: v1(1537,656) 1537,856 1447.81,945.19 1447.81,1305.81 1553.51,1411.51 1553.51,1596.49 v1(1552,1598)
  L08 - BOTTOM w4.5: v1(1552,1598) 1553,1599 1553,1841.27 1540.75,1853.52 1540.75,2059.15 2237.6,2756 2471,2756 2588,2873 v1(2588,2995)
AM261_USB0_VBUS_OC: R141.2 U2.F2 U38.3 | length 3543.1
  L01 - TOP w3.5: U2.F2@2640.27,956.46 2652.84,943.88 2681.78,943.88 2684.55,946.65 2710.7,946.65 2725.85,931.5 2785.5,931.5 v1(2787,930)
  L01 - TOP w4.5: v1(3052,3185) 3052,3210.62 R141.2@3055.38,3214
  L01 - TOP w6: U38.3@3054.87,3265.6 3054.87,3214.51 R141.2@3055.38,3214
  L06 - SIG w4.5: v1(2787,930) 2798.94,918.06 2802.67,918.06 2803.85,919.25 2818.15,919.25 2828.25,909.15 2828.25,894.85 2827.06,893.67 2827.06,889.94 2852.25,864.75 3156.65,864.75 3168.4,853 3467,853 3553,939 3553,1677 3095.25,2134.75 3095.25,3141.75 v1(3052,3185)
AM261_WARMRSTN: Q14.1 R214.1 R215.2 U2.G3 U4.2 U29.2 U47.2 | length 4275.5
  L01 - TOP w4.5: R215.2@1457.92,246.46 R214.1@1457.92,278.46 1458.46,279 1504,279 v1(1529,254) ; Q14.1@1818.2,262.89 1818.2,274.56 1827,283.36 v1(1827,286) 1828.44,287.44 1842.75,287.44 1937,381.69 1937,598.66 1953.87,615.54 1964.87,615.54 U47.2@1967.77,618.44 ; v1@2753,516 2854,516 3073,735 v1(3142,735)
  L06 - SIG w4.5: v1@1937,537 2252.4,537 2261.65,527.75 2374.35,527.75 2376.85,530.25 2740,530.25 v1(2753.62,516.62) ; v1(2614.68,982.05) 2614.68,1013.44 2617.31,1016.08 2647.37,1016.08 2663.66,1032.36 2667.38,1032.36 2681.9,1017.85 2696.1,1017.85 2706.15,1027.9 2706.15,1057.49 2693.41,1070.23 2693.41,1103.56 2729.83,1139.98 2788.5,1198.65 3079.35,1198.65 v1(3180,1098)
  L08 - BOTTOM w4.3: U4.2@2685.35,1500 2685.85,1499.5 2714.5,1499.5 2715,1499
  L08 - BOTTOM w4.5: v1(1529,254) 1529,230.6 1587.85,171.75 1762.15,171.75 1827,236.6 v1(1827,286) ; 2715,1499 2733,1481 2733,1302.37 2820.37,1215 3046.15,1215 3065.31,1195.84 3065.31,1170.29 3073.97,1161.62 3085.65,1161.62 3100.74,1146.53 3101.41,1146.53 3107.4,1140.55 3107.4,1122.59 3133.41,1096.58 3178.58,1096.58 v1(3180,1098) 3228.25,1049.75 3228.25,821.25 v1(3142,735)
  other v1: 1937.62,537.62
CLK_25M_MCU: R20.2 U2.Y3 | length 252.9
  L01 - TOP w4.5: R20.2@2399.23,1377.5 2401,1375.72 2401,1366.89 2401,1356.1 2403.64,1353.47 2574.6,1353.47 2613.34,1314.72 U2.Y3@2614.68,1314.72
CLK_25M_SOM-ETH1: R19.2 U9_SOM-ETH1.9 | length 710.7
  L01 - TOP w4.3: v1(1660,1273) 1662.62,1275.62 1672.27,1275.62 1687.75,1291.1 U9_SOM-ETH1.9@1687.75,1297.99
  L06 - SIG w4.5: v1(1660,1273) 1680.61,1252.39 1918.88,1252.39 2165.49,1499 2217.46,1499 v1(2217.74,1498.72)
CLK_25M_SOM-ETH2: R18.2 U9_SOM-ETH2.9 | length 942.8
  L01 - TOP w4.3: v1(1637,855) 1639.62,852.38 1652.45,852.38 1655.74,849.09 1664.86,849.09 1670.77,854.99 U9_SOM-ETH2.9@1686.75,854.99
  L06 - SIG w4.5: v1(1974,1227) 1992.4,1227 2006.97,1241.57 2006.97,1282.51 2191.17,1466.72 v1(2217.74,1466.72)
  L08 - BOTTOM w4.5: v1(1637,855) 1637,887.92 1792.01,1042.93 1808.33,1042.93 1974,1208.6 v1(1974,1227)
COL_SOM-ETH1: U2.J19 U9_SOM-ETH1.28 | length 891.7
  L01 - TOP w4.3: U9_SOM-ETH1.28@1766.49,1486.97 1767.6,1488.08 1767.6,1516.53 v1(1768.7,1517.64)
  L08 - BOTTOM w4.3: v1(1768.7,1517.64) 1785.86,1534.79 1935.47,1534.79 2046.3,1423.95 2046.3,1130.7 2071.15,1105.85 2071.15,1067.6 2121.94,1016.8 2188.8,1016.8 v1(2205.85,1033.85)
COL_SOM-ETH2: U2.E20 U9_SOM-ETH2.28 | length 869.7
  L01 - TOP w4.3: U9_SOM-ETH2.28@1765.49,1043.97 1766.6,1045.08 1766.6,1073.53 v1(1767.7,1074.64) ; v1(2151,927) 2153.05,929.05 2177.82,929.05 U2.E20@2179.64,930.87
  L03 - SIG w4.5: v1(1767.7,1074.64) 1767.7,1037.31 1706.06,975.66 1706.06,861.32 1768.29,799.09 1907.75,799.09 1936.66,828 2072.87,828 2075.5,830.64 2075.5,897.69 2112.06,934.25 2141.61,934.25 2148.86,927 v1(2151,927)
CPSW_MDIO0_MDC: U2.T18 U5.4 | length 802.2
  L06 - SIG w4.5: v1(1582,1328) 1582,1307.6 1647.72,1241.89 1893.11,1241.89 1926,1209 2072.04,1209 2103.75,1240.71 2103.75,1252.15 2114.38,1262.77 2127.47,1262.77 2180.41,1262.77 v1(2230.82,1212.36)
  L08 - BOTTOM w4.3: U5.4@1574,1289 1574,1318.09 1582,1326.09 v1(1582,1328)
CPSW_MDIO0_MDIO: U2.R17 U53.3 | length 726.3
  L01 - TOP w4.5: U53.3@1586.2,1171.16 v1(1586.22,1188.25)
  L06 - SIG w4.5: v1(1586.22,1188.25) 1627.85,1188.25 1631.85,1192.25 1677.44,1192.25 1686.94,1182.75 1854.15,1182.75 1861.29,1189.89 2067.78,1189.89 2103.04,1225.15 2191.1,1225.15 2229.48,1186.77 v1(2256.41,1186.77)
CPSW_MDIO0_MDIO_3V3: U5.2 U53.4 | length 140.8
  L03 - SIG w4.5: v1(1527,1327) 1527,1311.07 v1(1586.2,1251.87)
  L08 - BOTTOM w4.3: v1(1527,1327) 1527,1325.72 1534.63,1318.09 U5.2@1534.63,1289
CRS_SOM-ETH1: R30_SOM-ETH1.2 U2.J20 U9_SOM-ETH1.29 | length 913.7
  L01 - TOP w4.3: R30_SOM-ETH1.2@1739.13,1548.76 1742.56,1545.34 v1(1742.56,1517.64) 1744.68,1515.52 1744.68,1489.09 U9_SOM-ETH1.29@1746.8,1486.97
  L08 - BOTTOM w4.3: v1(1742.56,1517.64) 1785.92,1561 1932,1561 2082,1411 2082,1300.85 2086.75,1296.1 2086.75,1220.45 2078.85,1212.55 2078.85,1132.04 2127.47,1083.42 2152.39,1058.5 2155.61,1058.5 2157.07,1057.05 2162.06,1057.05 2172.05,1047.06 2172.05,1043.22 2180.26,1035.01 v1(2180.26,1033.85)
CRS_SOM-ETH2: R30_SOM-ETH2.2 U2.E19 U9_SOM-ETH2.29 | length 951
  L01 - TOP w3.5: v1(2123,917) 2126.92,917 2133.57,910.35 2158.35,910.35 2165.85,917.85 2192.21,917.85 U2.E19@2205.23,930.87
  L01 - TOP w4.3: R30_SOM-ETH2.2@1738.13,1105.76 1741.56,1102.34 v1(1741.56,1074.64) 1743.68,1072.52 1743.68,1046.09 U9_SOM-ETH2.29@1745.8,1043.97
  L03 - SIG w4.5: v1(1741.56,1074.64) 1741.56,1037.49 1695.56,991.49 1695.56,856.97 1763.94,788.59 2074.59,788.59 2094.4,808.4 2094.4,885.89 2123,914.49 v1(2123,917)
EARTH_GND: C110.1 J2.11 J2.12 J3.11 J3.12 J4.1 R88.2
  other v1: 387,218.92 434.59,218.82 479,218.92 388,259.96 434,259.96 478,259.96 389,300.92 435,300.92 478,300.92 293,349 60,351 565,380 293,446.35 60,448.35 565,477.35 293,543.71 60,545.71 565,574.71 293,641.06 60,643.06 565,672.06 293,738.41 60,740.41 565,769.41 293,835.76 60,837.76 565,866.76 293,933.12 60,935.12 387,939 434.59,938.9 479,939 388,980.04 434,980.04 478,980.04 389,1021 435,1021 478,1021 293,1030.47 60,1032.47 293,1127.82 443,1154 443,1191 574,1197.68 293,1225.18 443,1228 573.2,1237.68 442,1265 573,1276.68 442,1302 293,1322.53 442,1339 293,1419.88 60,1421.88 387,1458.92 434.59,1458.82 479,1458.92 388,1499.96 434,1499.96 478,1499.96 293,1517.23 60,1519.23 389,1540.92 435,1540.92 478,1540.92 570,1606 293,1614.59 60,1616.59 570,1703.35 293,1711.94 60,1713.94 570,1800.71 293,1809.29 60,1811.29 570,1898.06 293,1906.65 60,1908.65 570,1995.41 293,2004 60,2006 570,2092.76 387,2179 434.59,2178.9 479,2179 388,2220.04 434,2220.04 478,2220.04 389,2261 435,2261 478,2261
ETH0_LED_ACT: Q7.1 R29_SOM-ETH1.2 U9_SOM-ETH1.30 | length 860.4
  L01 - TOP w4.3: Q7.1@1011.8,1627.11 1014.73,1627.11 1022.22,1619.62 1029.38,1619.62 v1(1032,1617) ; R29_SOM-ETH1.2@1706.13,1548.76 1706.13,1546.8 1716.42,1536.51 v1(1716.42,1517.64) 1716.42,1515.99 1727.12,1505.3 U9_SOM-ETH1.30@1727.12,1486.97
  L03 - SIG w4.5: v1(1032,1617) 1081.2,1567.8 1496,1567.8 1594.39,1469.4 1668.19,1469.4 v1(1716.42,1517.64)
ETH0_LED_LINK: Q5.1 R28_SOM-ETH1.1 R201_SOM-ETH1.2 U2.J18 U9_SOM-ETH1.31 | length 1997.2
  L01 - TOP w4.3: Q5.1@1011.02,2027.11 1023.89,2027.11 v1(1033,2018) ; R201_SOM-ETH1.2@1673.13,1548.76 1673.13,1546.8 1687.33,1532.6 1687.33,1520.58 v1(1690.28,1517.64) 1704.66,1503.25 1704.66,1489.74 U9_SOM-ETH1.31@1707.43,1486.97
  L03 - SIG w4.5: v1(1033,2018) 1236,2018 1690.28,1563.72 v1(1690.28,1517.64)
  L08 - BOTTOM w4.3: R28_SOM-ETH1.1@1673.13,1548.76 1673.13,1546.8 1687.33,1532.6 1687.33,1520.58 v1(1690.28,1517.64) 1690.28,1520.03 1771.03,1600.79 1906.78,1600.79 2092.3,1415.27 2092.3,1377.95 2174.05,1296.2 2174.05,1094.95 2192.51,1076.49 2212.92,1076.49 2222.9,1066.51 2222.9,1046.1 2231.44,1037.56 v1(2231.44,1033.85)
ETH0_RD_N: C78_SOM-ETH1.1 J2.3 U9_SOM-ETH1.4 U17.5 | length 1206.5
  L01 - TOP w3.5: J2.3@893.84,1985 905.11,1973.73 941.02,1973.73 970.75,1944.01 970.75,1942.6 972.8,1940.55 980.3,1940.55 992.57,1928.27 992.57,1919.12 999.69,1912 1086.1,1912 1118,1880.1 1289.5,1880.1 1339,1830.6 1339,1538 1497.91,1379.09 1587.6,1379.09 1606.55,1398.03 1650.86,1398.03 1655.15,1402.32 U9_SOM-ETH1.4@1662.16,1402.32
  other v1: 1234,1888
ETH0_RD_P: C77_SOM-ETH1.1 J2.5 U9_SOM-ETH1.5 U17.1 | length 1206.5
  L01 - TOP w3.5: J2.5@893.84,1885 905.11,1896.27 941.02,1896.27 970.75,1925.99 970.75,1927.4 972.8,1929.45 975.7,1929.45 981.47,1923.68 981.47,1914.52 995.1,1900.9 1081.5,1900.9 1113.4,1869 1284.9,1869 1327.9,1826 1327.9,1533.4 1461.15,1400.15 1493.32,1367.99 1592.2,1367.99 1611.15,1386.93 1650.86,1386.93 1655.15,1382.64 U9_SOM-ETH1.5@1662.16,1382.64
  other v1: 1201,1860
ETH0_TD_N: C80_SOM-ETH1.1 J2.6 U9_SOM-ETH1.6 U17.3 | length 1184.4
  L01 - TOP w3.5: J2.6@893.84,1835 905.11,1823.73 942.02,1823.73 971.75,1794.01 971.75,1792.6 973.8,1790.55 999.88,1790.55 1015.1,1805.77 1058.94,1805.77 1089.27,1836.1 1255.6,1836.1 1291,1800.7 1291,1496.1 1428.44,1358.66 1650.86,1358.66 1655.15,1362.95 U9_SOM-ETH1.6@1662.16,1362.95
  other v1: 1234,1844
ETH0_TD_P: C79_SOM-ETH1.1 J2.8 U9_SOM-ETH1.7 U17.4 | length 1184.4
  L01 - TOP w3.5: J2.8@893.84,1735 905.11,1746.27 942.02,1746.27 971.75,1775.99 971.75,1777.4 973.8,1779.45 1004.48,1779.45 1019.7,1794.67 1063.54,1794.67 1093.87,1825 1251,1825 1271,1805 1279.9,1796.1 1279.9,1491.5 1423.84,1347.56 1650.86,1347.56 1655.15,1343.27 U9_SOM-ETH1.7@1662.16,1343.27
  other v1: 1201,1817
ETH1_LED_ACT: Q8.1 R29_SOM-ETH2.2 U9_SOM-ETH2.30 | length 1117.1
  L01 - TOP w4.3: R29_SOM-ETH2.2@1705.13,1105.76 1705.13,1103.8 1715.42,1093.51 v1(1715.42,1074.64) 1715.42,1072.99 1726.12,1062.3 U9_SOM-ETH2.30@1726.12,1043.97
  L01 - TOP w4.5: Q8.1@1011.02,388.11 1012.58,386.56 1031.44,386.56 v1(1033,385)
  L03 - SIG w4.5: v1(1033,385) 1120.22,385 1649.38,914.17 1649.38,1008.6 v1(1715.42,1074.64)
ETH1_LED_LINK: Q6.1 R28_SOM-ETH2.1 R201_SOM-ETH2.2 U2.G18 U9_SOM-ETH2.31 | length 1499.9
  L01 - TOP w4.3: R201_SOM-ETH2.2@1672.13,1105.76 1672.13,1103.8 1686.33,1089.6 1686.33,1077.58 v1(1689.28,1074.64) 1703.66,1060.25 1703.66,1046.74 U9_SOM-ETH2.31@1706.43,1043.97
  L01 - TOP w4.5: Q6.1@1011.02,788.11 1011.47,788.56 1051.56,788.56 v1(1052,789) ; v1(2230,998) 2230.41,997.59 2230.41,982.46 U2.G18@2230.82,982.05
  L03 - SIG w4.5: v1(1052,789) 1403.64,789 v1(1689.28,1074.64)
  L06 - SIG w4.5: v1(1689.28,1074.64) 1728.07,1035.84 2098.55,1035.84 2107.65,1026.75 2138.5,1026.75 2167.25,998 v1(2230,998)
  L08 - BOTTOM w4.3: R28_SOM-ETH2.1@1672.13,1105.76 1672.13,1103.8 1686.33,1089.6 1686.33,1077.58 v1(1689.28,1074.64)
ETH1_RD_N: C78_SOM-ETH2.1 J3.3 U9_SOM-ETH2.4 U57.5 | length 952.7
  L01 - TOP w3.5: J3.3@893.84,745 905.14,733.71 939.05,733.71 968.75,704.01 968.75,694.83 979.92,683.66 979.92,680.88 981.97,678.83 1058.6,678.83 1061.85,675.58 1090.33,647.1 1116.15,647.1 1116.55,647.5 1126.23,647.5 U57.5@1136.13,657.4 1146.04,647.5 1155.72,647.5 1156.12,647.1 1299.24,647.1 1607.17,955.03 1649.86,955.03 1654.15,959.32 U9_SOM-ETH2.4@1661.16,959.32
  other v1: 1234,654
ETH1_RD_P: C77_SOM-ETH2.1 J3.5 U9_SOM-ETH2.5 U57.1 | length 931.9
  L01 - TOP w3.5: J3.5@893.84,645 905.14,656.29 939.05,656.29 963.87,681.11 966.77,681.11 968.82,679.06 968.82,676.28 977.37,667.73 1027.87,667.73 1054,667.73 1085.73,636 1303.84,636 1611.77,943.93 1649.86,943.93 1654.15,939.64 U9_SOM-ETH2.5@1661.16,939.64
  other v1: 1202,629
ETH1_TD_N: C80_SOM-ETH2.1 J3.6 U9_SOM-ETH2.6 U57.3 | length 955.1
  L01 - TOP w3.5: J3.6@893.84,595 905.14,583.71 939.05,583.71 968.75,554.01 968.75,552.6 970.8,550.55 975.75,550.55 995,569.8 1021.35,569.8 ; U57.3@1027.87,582.6 1021.35,576.08 1021.35,569.8 ; U9_SOM-ETH2.6@1661.16,919.95 1654.15,919.95 1649.86,915.66 1606.81,915.66 1296.25,605.1 1102.1,605.1 1098.85,601.85 1095.6,598.6 1066.8,569.8 1021.35,569.8
  other v1: 1234,612
ETH1_TD_P: C79_SOM-ETH2.1 J3.8 U9_SOM-ETH2.7 U57.4 | length 939.6
  L01 - TOP w3.5: J3.8@893.84,495 905.14,506.29 939.05,506.29 968.75,535.99 968.75,537.4 970.8,539.45 980.35,539.45 999.59,558.7 1071.39,558.7 1106.7,594 1300.85,594 1611.41,904.56 1649.86,904.56 1654.15,900.27 U9_SOM-ETH2.7@1661.16,900.27
  other v1: 1202,587
FSIRX0_CLK: J9.1 U27.1 | length 617.6
  L01 - TOP w4.5: J9.1@4400,104 4400,146.4 4440.73,187.13 4440.73,426.27 4360,507 4360,594.4 4384.85,619.25 4399.15,619.25 4401.77,616.62 U27.1@4425.47,616.62
FSIRX0_DATA0: J9.5 U27.8 | length 492
  L01 - TOP w4.5: U27.8@4478.62,545.76 4478.62,537.88 4554.92,461.58 4554.92,191.48 4600,146.4 J9.5@4600,104
FSIRX0_DATA1: J9.7 U27.4 | length 747.3
  L01 - TOP w4.5: U27.4@4423.5,569.38 4415.63,569.38 4383,536.75 4383,516 4540.73,358.27 4540.73,100.27 4577.73,63.27 4618.74,63.27 4619.31,63.84 4654.92,63.84 4695.08,104 J9.7@4700,104
FSITX0_CLK: J9.2 U26.8 | length 383.3
  L01 - TOP w4.5: U26.8@4299.62,545.76 4299.62,525.77 4400,425.4 J9.2@4400,204
FSITX0_DATA0: J9.6 U26.1 | length 692.8
  L01 - TOP w4.5: U26.1@4246.47,616.62 4224.77,616.62 4222.15,619.25 4207.85,619.25 4188.25,599.65 4188.25,514.75 v1(4287,416)
  L08 - BOTTOM w4.5: v1(4287,416) 4384.15,416 4596.15,204 J9.6@4600,204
